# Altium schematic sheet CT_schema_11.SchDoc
size 278 x 170 mm
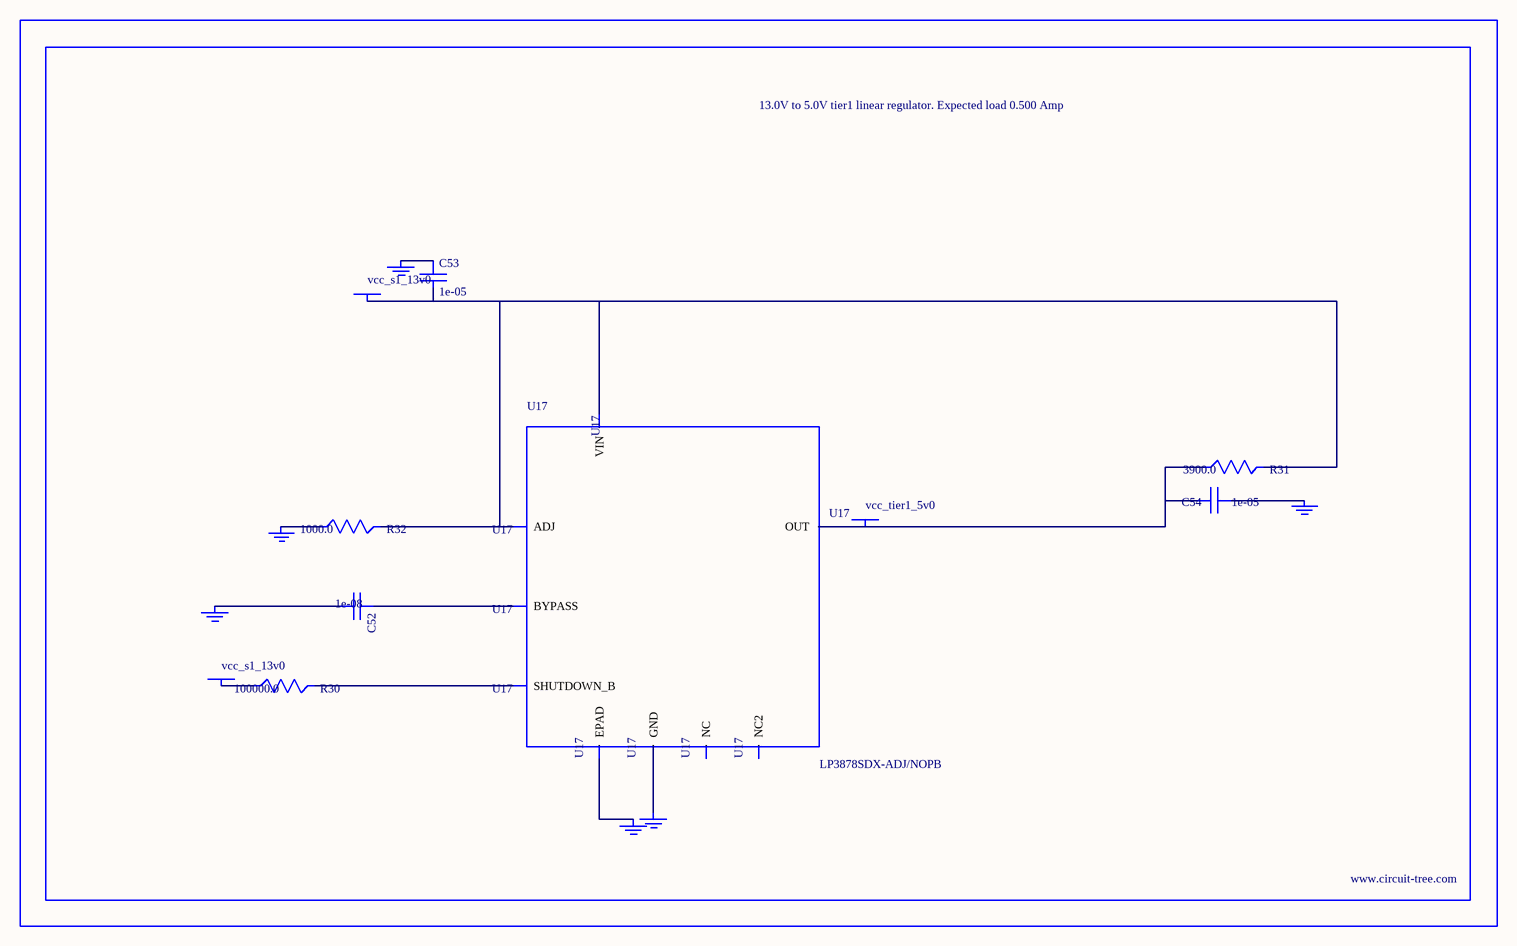
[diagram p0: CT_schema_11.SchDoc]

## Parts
BORDER10  (no value)
C52  1e-08  [C0402]
C53  1e-05  [C1210]
C54  1e-05  [C1210]
GND_INSTANCE_10_0  (no value)
GND_INSTANCE_10_1  (no value)
GND_INSTANCE_10_2  (no value)
GND_INSTANCE_10_3  (no value)
GND_INSTANCE_10_4  (no value)
GND_INSTANCE_10_5  (no value)
POWER_INSTANCE_10_0  vcc_s1_13v0
POWER_INSTANCE_10_1  vcc_s1_13v0
POWER_INSTANCE_10_2  vcc_tier1_5v0
R30  100000.0  [R0603]
R31  3900.0  [R0603]
R32  1000.0  [R0603]
U17  LP3878SDX-ADJ/NOPB  [WSON-8]

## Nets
NetC52_1: C52.1 U17.1(BYPASS)
NetC52_2: C52.2 GND_INSTANCE_10_0.0(GND)
NetC53_1: C53.1 GND_INSTANCE_10_1.0(GND)
NetC53_2: C53.2 POWER_INSTANCE_10_0.0(PWR) R31.2 R32.2 U17.4(VIN) U17.6(ADJ)
NetC54_1: C54.1 GND_INSTANCE_10_2.0(GND)
NetC54_2: C54.2 POWER_INSTANCE_10_2.0(PWR) R31.1 U17.5(OUT)
NetGND_INSTANCE_10_3_0: GND_INSTANCE_10_3.0(GND) R32.1
NetGND_INSTANCE_10_4_0: GND_INSTANCE_10_4.0(GND) U17.PAD(EPAD)
NetGND_INSTANCE_10_5_0: GND_INSTANCE_10_5.0(GND) U17.3(GND)
NetPOWER_INSTANCE_10_1_0: POWER_INSTANCE_10_1.0(PWR) R30.1
NetR30_2: R30.2 U17.8(SHUTDOWN_B)

Not connected (* = marked no-connect by the designer): U17 2(NC) 7(NC2)

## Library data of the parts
BORDER10 = BORDER_PAGE10
C52 = C0402C103K3RAC
C53 = C1210C106K5PACTU
C54 = GRM32DR61E106MA12L
GND_INSTANCE_10_0-GND_INSTANCE_10_5 = GND
POWER_INSTANCE_10_0-POWER_INSTANCE_10_2 = PWR
R30 = RC0603JR-07100KL
R31 = RC0603JR-073K9L
R32 = RC0603JR-071KL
